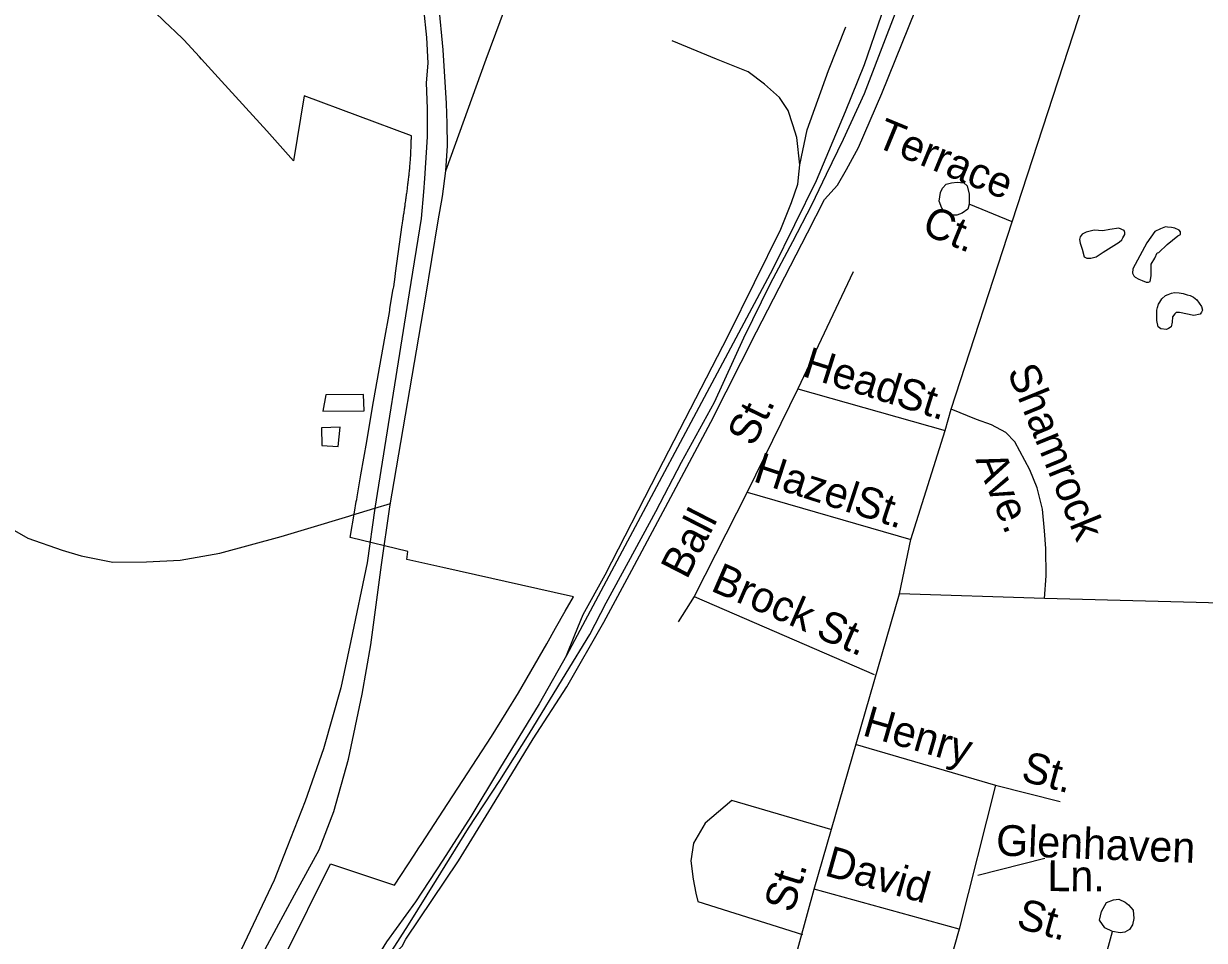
# Model space of a CAD drawing. Extents: x 2260773 to 2342389, y 552869 to 618546.
# Drawn here: x 2293706 to 2297350, y 585563 to 588391 of the extents above; entities that cross this region are included whole.
import ezdxf

# ---------------------------------------------------------------- set-up
doc = ezdxf.new("R2010")
doc.units = 0
for name, color, linetype in [('Exist Boundary Political City Limit New', 7, 'Continuous'), ('Exist Hydrographic Misc Water Feature', 7, 'Continuous'), ('Exist Railroad Mainline', 7, 'Continuous'), ('Exist Railroad Siding', 7, 'Continuous'), ('Exist Road Non-System Type 51', 7, 'Continuous'), ('Exist Road Non-System Type 51 Label', 7, 'Continuous'), ('Exist Road Primary Interstate Ramp 1 Lane Attributed', 7, 'Continuous'), ('Exist Road Primary US Divided Attributed', 7, 'Continuous'), ('Exist Road Secondary Type 51 Attributed', 7, 'Continuous'), ('Exist Road Secondary Type 51 Label', 7, 'Continuous'), ('Map Preparation Boundary City Limit Buffer Line', 7, 'Continuous')]:
    doc.layers.add(name, color=color, linetype=linetype)

msp = doc.modelspace()

# ---------------------------------------------------------------- linework, layer by layer
at = {"layer": 'Exist Boundary Political City Limit New'}
for points in [[(2294900.8, 587987.3), (2294901, 587991.9), (2294901.2, 587996.4), (2294901.2, 588001), (2294901.5, 588005.6), (2294901.8, 588010.1), (2294902, 588014.7), (2294902, 588019.2), (2294902.2, 588023.8), (2294902.2, 588031.8), (2294902.5, 588035.2), (2294902.5, 588044.1), (2294571.2, 588168.4), (2294538.2, 587967.1), (2294456.5, 588059.8), (2294316.8, 588213.4), (2294255.2, 588280.7), (2294248.8, 588287.8), (2294200.5, 588340.7), (2294171.2, 588368.8), (2294160.5, 588378.9), (2294066.2, 588469.2)], [(2294910.8, 585825.4), (2294925.8, 585848.2), (2294934.8, 585861.8), (2295000, 585961.2), (2295061.2, 586056.6), (2295150.2, 586192.3), (2295195.2, 586264.8), (2295233.2, 586326.2), (2295320.2, 586478), (2295347.5, 586525.8), (2295377.5, 586578.2), (2295402.8, 586622.4), (2295343, 586635.8), (2295000, 586713.1), (2294888, 586737.6), (2294891.2, 586762.5), (2294713.2, 586806.1), (2294726.8, 586883.3), (2294732.5, 586916.2), (2294733.8, 586923.3), (2294735, 586931.5), (2294746.8, 586998.9), (2294764.8, 587101.9), (2294783, 587207.3), (2294801.2, 587311.8), (2294819.5, 587415.3), (2294834.5, 587500), (2294835.8, 587506.8), (2294836, 587509.7), (2294836, 587511.6), (2294846, 587572.2), (2294847, 587574.9), (2294848.5, 587578.8), (2294852.2, 587610.1), (2294853.8, 587621.4), (2294874, 587769.7), (2294874.8, 587774.1), (2294875.5, 587777.6), (2294875.8, 587781), (2294876.5, 587784.4), (2294876.8, 587787.8), (2294877.5, 587792.3), (2294878.2, 587795.7), (2294878.5, 587799.1), (2294879.2, 587803.6), (2294879.8, 587807), (2294880.2, 587810.4), (2294880.5, 587811.5), (2294881, 587814.9), (2294881.5, 587819.4), (2294882, 587822.8), (2294882.5, 587826.2), (2294882.8, 587827.3), (2294883.2, 587830.8), (2294883.8, 587835.2), (2294884.5, 587839.8), (2294885, 587844.3), (2294885.8, 587848.8), (2294886.2, 587852.2), (2294886.5, 587855.6), (2294887.2, 587860.1), (2294887.8, 587864.7), (2294888.5, 587868.1), (2294889, 587871.4), (2294889.2, 587876), (2294890, 587880.5), (2294890.5, 587883.9), (2294890.8, 587887.3), (2294891.5, 587891.8), (2294891.8, 587893), (2294892, 587896.4), (2294892.5, 587899.8), (2294893, 587903.1), (2294893.5, 587907.7), (2294894, 587912.2), (2294894.5, 587915.6), (2294894.5, 587916.8), (2294894.8, 587917.9), (2294895, 587920.2), (2294895, 587921.3), (2294895.2, 587922.4), (2294895.5, 587924.7), (2294895.5, 587925.8), (2294895.8, 587927), (2294896, 587930.4), (2294896.5, 587934.9), (2294897, 587939.5), (2294897.5, 587942.9), (2294897.8, 587946.3), (2294898, 587949.7), (2294898.2, 587952), (2294898.2, 587953.1), (2294898.8, 587957.7), (2294899, 587961.1), (2294899.2, 587964.5), (2294899.5, 587968.9), (2294899.8, 587973.6), (2294900.2, 587978.2), (2294900.5, 587982.8), (2294900.8, 587987.3)], [(2294511.8, 585515.6), (2294653, 585798.9), (2294850.5, 585732.9), (2294910.8, 585825.4)]]:
    msp.add_lwpolyline(points, dxfattribs=at)
at = {"layer": 'Exist Hydrographic Misc Water Feature'}
for points in [[(2296964.5, 587724.7), (2296966.8, 587713.1), (2296972.7, 587695.1), (2296978.9, 587671.1), (2296986.7, 587667.1), (2296999.2, 587667.2), (2297015.2, 587671.3), (2297036.9, 587685.4), (2297086.7, 587716.1), (2297094.5, 587724.2), (2297098.4, 587730.1), (2297104.4, 587740.2), (2297104.2, 587746.3), (2297102.1, 587752.3), (2297085.9, 587760), (2297058, 587755.7), (2297036.1, 587751.7), (2297010, 587753.6), (2296984.4, 587747.3), (2296972.7, 587740.9), (2296966.4, 587733), (2296964.5, 587724.7)], [(2297196.4, 587749), (2297172.4, 587714.9), (2297129.2, 587634.6), (2297127.3, 587620.7), (2297131.4, 587612.4), (2297135.5, 587608.6), (2297147.4, 587602.7), (2297157.7, 587598.7), (2297170, 587592.8), (2297177.6, 587592.9), (2297181.9, 587595.1), (2297185.2, 587613.2), (2297185.4, 587639.2), (2297185.2, 587648.9), (2297197.1, 587667), (2297204.4, 587683.3), (2297208.7, 587685.2), (2297234.4, 587709.7), (2297268, 587735.8), (2297276, 587739.9), (2297276, 587748), (2297271.9, 587753.9), (2297258, 587759.6), (2297247.7, 587761.6), (2297236.2, 587763.3), (2297229.9, 587763.5), (2297213.9, 587757.3), (2297196.4, 587749)], [(2297326.2, 587538.5), (2297340.4, 587518.5), (2297344.3, 587506.6), (2297340.4, 587500.7), (2297336.3, 587494.8), (2297316.6, 587490.5), (2297272.7, 587499.9), (2297262.5, 587499.9), (2297258.4, 587496), (2297250.8, 587485.8), (2297250.6, 587470), (2297247.1, 587455.9), (2297238.9, 587449.9), (2297232.9, 587447.5), (2297214.9, 587449.4), (2297206.9, 587455.5), (2297202.6, 587475.2), (2297202.4, 587507.2), (2297204.6, 587515.4), (2297207.9, 587525.5), (2297212.4, 587531.3), (2297218.4, 587541.4), (2297229.9, 587551.8), (2297237.7, 587555.5), (2297247.7, 587559.6), (2297257.7, 587561.8), (2297271.9, 587560), (2297284, 587558.2), (2297296.1, 587554), (2297305.9, 587552.1), (2297316, 587546.5), (2297326.2, 587538.5)], [(2294628.8, 587195.3), (2294756.5, 587196.7), (2294754.3, 587246.6), (2294638.4, 587245.3), (2294628.8, 587195.3)], [(2294626.1, 587089.4), (2294676.1, 587086), (2294683.1, 587145.8), (2294625.3, 587143.5), (2294626.1, 587089.4)]]:
    msp.add_lwpolyline(points, dxfattribs=at)
at = {"layer": 'Exist Railroad Mainline'}
for points in [[(2296169.2, 591130), (2296437.4, 589781.5), (2296454.2, 589709.6), (2296468.7, 589647.9), (2296473.4, 589565.9), (2296486.4, 589464), (2296493.5, 589340.1), (2296498.4, 589238.3), (2296491.7, 589102.3), (2296481, 588970.3), (2296466, 588852.3), (2296437.4, 588714.1), (2296406.6, 588591.8), (2296352.2, 588415.3), (2296299.8, 588263.1), (2296241.1, 588118.5), (2296151.2, 587905.8), (2296017.8, 587634.6), (2295381.3, 586441.3)], [(2294816.7, 585490.5), (2294893.5, 585611.1), (2294980.1, 585749.9), (2295078.7, 585908.9), (2295175.2, 586055.7), (2295265.7, 586200.4), (2295379.8, 586387.4), (2295452.8, 586506.1), (2295503.8, 586604.4), (2295572.5, 586731), (2295657, 586885.8), (2295735.6, 587038.3), (2295837.7, 587223.2), (2295927.9, 587421.9), (2296010.2, 587588.6), (2296079.1, 587719.1), (2296137.9, 587831.7), (2296183, 587926.2), (2296236, 588034.4), (2296300.6, 588175.1), (2296370.9, 588357.6), (2296454.6, 588576.2)], [(2295381.3, 586441.3), (2295296.9, 586292.7), (2295174.7, 586091.7), (2295086.2, 585944.9), (2294999.5, 585810.1), (2294914.7, 585681.5), (2294826.1, 585558.5), (2294735.3, 585411.8)]]:
    msp.add_lwpolyline(points, dxfattribs=at)
at = {"layer": 'Exist Railroad Siding'}
for points in [[(2294816.7, 585490.5), (2294874.2, 585545.1), (2294885.8, 585567.1), (2295047.4, 585808.5), (2295149.9, 585973.4), (2295278, 586184.5), (2295382.4, 586345.4), (2295496.3, 586544.4), (2295582.8, 586705.2), (2295702.7, 586930.1), (2295826.3, 587161.1), (2295967.7, 587440.3), (2296124.8, 587745.6), (2296177.6, 587848.1), (2296217.3, 587892.5), (2296244.9, 587940.7), (2296282.2, 588008.9), (2296354.6, 588175.6), (2296563.6, 588695.2)], [(2296100.8, 587955.2), (2296123.8, 588063.5), (2296190.1, 588245.9), (2296242.8, 588380.4)], [(2296100.8, 587955.2), (2296091.9, 588039.2), (2296079.5, 588079), (2296065.2, 588122.9), (2296038.8, 588162.6), (2295992.5, 588204.1), (2295942.1, 588241.7), (2295843.9, 588280.7), (2295707.3, 588337.4)], [(2295381.3, 586441.3), (2295406.8, 586505.6), (2295432.2, 586567.7), (2295500.9, 586690.4), (2295663.9, 587009.6), (2295879.8, 587427.5), (2296042.6, 587756.9), (2296075.9, 587839.2), (2296095.4, 587895.3), (2296099, 587935.3), (2296100.8, 587955.2)]]:
    msp.add_lwpolyline(points, dxfattribs=at)
at = {"layer": 'Exist Road Non-System Type 51'}
for p, q in [((2296756, 587779.6), (2296623.6, 587834.3)), ((2296266.2, 587625.5), (2296095.3, 587263.7)), ((2296095.3, 587263.7), (2295938.7, 586945.1)), ((2296095.3, 587263.7), (2296549.4, 587135.8)), ((2295938.7, 586945.1), (2295775.5, 586623.6)), ((2295938.7, 586945.1), (2296443.7, 586799.5)), ((2294790, 586896.3), (2294837.8, 586910.7)), ((2294583.1, 586833.8), (2294709, 586871.8)), ((2294709, 586871.8), (2294718.5, 586874.7)), ((2294718.5, 586874.7), (2294790, 586896.3)), ((2295775.5, 586623.6), (2295725.9, 586545.2)), ((2295775.5, 586623.6), (2296330.2, 586383.3)), ((2296271.5, 586168.5), (2296704.8, 586041.8)), ((2296704.8, 586041.8), (2296592.5, 585597.9)), ((2296704.8, 586041.8), (2296904.4, 585990.9)), ((2296592.5, 585597.9), (2296145.8, 585721)), ((2296592.5, 585597.9), (2296468.5, 585159.7))]:
    msp.add_line(p, q, dxfattribs=at)
for points in [[(2296623.6, 587834.3), (2296619.8, 587818.2), (2296601.8, 587806.1), (2296585.9, 587799.9), (2296567.9, 587799.8), (2296549.9, 587807.6), (2296539.7, 587821.6), (2296531.6, 587843.3), (2296535.3, 587869.5), (2296541.2, 587883.5), (2296553, 587895.5), (2296568.9, 587899.8), (2296587, 587901.8), (2296606.9, 587900), (2296617.1, 587890.2), (2296623.4, 587864.3), (2296623.6, 587834.3)], [(2296856.1, 586617), (2296861.4, 586687.6), (2296860.1, 586771.5), (2296856.1, 586826.3), (2296850.2, 586892.9), (2296833.8, 586958.8), (2296811.1, 587014.4), (2296764.8, 587100.5), (2296737.4, 587129.2), (2296693, 587152.8), (2296646, 587169.7), (2296567.7, 587201.1)], [(2300809, 587184.6), (2300455.1, 587076.9), (2300325.3, 587042), (2300126.7, 586986.5), (2299640.5, 586848.9), (2299264.2, 586746.4), (2298958.6, 586655), (2298809.6, 586614), (2298742.5, 586595.4), (2298691.2, 586583.3), (2298580.2, 586579.4), (2298180.8, 586582.8), (2296856.1, 586617), (2296408.5, 586631.4)], [(2293518, 586913.7), (2293636.5, 586850.7), (2293718.9, 586803.6), (2293825.3, 586766.5), (2293883.3, 586749.1), (2293981.5, 586729.9), (2294085.5, 586731), (2294189.3, 586735.9), (2294311.1, 586757.1), (2294500.5, 586808.8), (2294583.1, 586833.8)], [(2296197.1, 585905.4), (2295891.7, 585994.8), (2295809.5, 585924.3), (2295772.9, 585862.9), (2295765.1, 585808.1), (2295771.6, 585751.9), (2295780.7, 585708.8), (2295786, 585682.7), (2296109.6, 585581.5)], [(2297066.3, 585590), (2297042.1, 585601.7), (2297025.8, 585625.6), (2297031.8, 585651.7), (2297047.3, 585679.7), (2297069.3, 585687.9), (2297085.3, 585690.2), (2297105.3, 585680.4), (2297115.3, 585672.4), (2297129.6, 585656.5), (2297131.9, 585630.4), (2297128.1, 585610.5), (2297118.2, 585596.3), (2297104.2, 585588.2), (2297090.2, 585586.1), (2297066.3, 585590)], [(2296916.2, 585034.4), (2297032.3, 585466), (2297066.3, 585590)]]:
    msp.add_lwpolyline(points, dxfattribs=at)
at = {"layer": 'Exist Road Non-System Type 51 Label'}
msp.add_lwpolyline([(2296856.9, 585815.9), (2296650.9, 585763.4)], dxfattribs=at)
at = {"layer": 'Exist Road Primary Interstate Ramp 1 Lane Attributed'}
msp.add_lwpolyline([(2295008.7, 587936.6), (2295133.7, 588281), (2295236.5, 588558.6), (2295262.7, 588657.6)], dxfattribs=at)
at = {"layer": 'Exist Road Primary US Divided Attributed'}
for points in [[(2294939.6, 588436.6), (2294949, 588347.5), (2294953.2, 588268.8), (2294948, 588208.1), (2294951.4, 588128.8), (2294951.4, 588041), (2294942.9, 587912.8), (2294939.6, 587872.3), (2294932.8, 587789.6), (2294895.7, 587560), (2294790, 586896.3), (2294766.2, 586728), (2294715.2, 586486.6), (2294684.9, 586341.5), (2294630.9, 586154.1), (2294575.2, 585992.1), (2294517.9, 585848.7), (2294479.1, 585749.1), (2294367.8, 585514.5)], [(2295008.7, 587936.6), (2295013.8, 588013.7), (2295012.5, 588082.5), (2295010.4, 588143.9), (2295000.1, 588310.1), (2294987, 588450.1)], [(2293381.4, 584211.6), (2293482.8, 584294.2), (2293779.3, 584588.3), (2294014.7, 584847), (2294200.8, 585101), (2294323.9, 585298.5), (2294430.2, 585497.6), (2294541.5, 585703.5), (2294617.4, 585841.9), (2294662.9, 585960), (2294708.5, 586122.1), (2294750.7, 586322.9), (2294777.6, 586474.8), (2294810.6, 586721.2), (2294836, 586900.3), (2294945.7, 587543.4), (2294985.3, 587782.5), (2294998.4, 587857.7), (2295008.7, 587936.6)]]:
    msp.add_lwpolyline(points, dxfattribs=at)
at = {"layer": 'Exist Road Secondary Type 51 Attributed'}
msp.add_lwpolyline([(2295809.5, 584493.6), (2296145.8, 585721), (2296408.5, 586631.4), (2296443.7, 586799.5), (2296549.4, 587135.8), (2296567.7, 587201.1), (2296756, 587779.6), (2297102.8, 588842.5), (2297171.1, 589045.3), (2297271.2, 589353.1), (2297362.5, 589635.1), (2297469.5, 589959.6), (2297516.5, 590114.3), (2297577.9, 590282.8), (2297741, 590769.2), (2297878, 591142)], dxfattribs=at)
at = {"layer": 'Map Preparation Boundary City Limit Buffer Line'}
for points in [[(2294900.8, 587987.3), (2294901, 587991.9), (2294901.2, 587996.4), (2294901.2, 588001), (2294901.5, 588005.6), (2294901.8, 588010.1), (2294902, 588014.7), (2294902, 588019.2), (2294902.2, 588023.8), (2294902.2, 588031.8), (2294902.5, 588035.2), (2294902.5, 588044.1), (2294571.2, 588168.4), (2294538.2, 587967.1), (2294456.5, 588059.8), (2294316.8, 588213.4), (2294255.2, 588280.7), (2294248.8, 588287.8), (2294200.5, 588340.7), (2294171.2, 588368.8), (2294160.5, 588378.9), (2294066.2, 588469.2)], [(2294910.8, 585825.4), (2294925.8, 585848.2), (2294934.8, 585861.8), (2295000, 585961.2), (2295061.2, 586056.6), (2295150.2, 586192.3), (2295195.2, 586264.8), (2295233.2, 586326.2), (2295320.2, 586478), (2295347.5, 586525.8), (2295377.5, 586578.2), (2295402.8, 586622.4), (2295343, 586635.8), (2295000, 586713.1), (2294888, 586737.6), (2294891.2, 586762.5), (2294713.2, 586806.1), (2294726.8, 586883.3), (2294732.5, 586916.2), (2294733.8, 586923.3), (2294735, 586931.5), (2294746.8, 586998.9), (2294764.8, 587101.9), (2294783, 587207.3), (2294801.2, 587311.8), (2294819.5, 587415.3), (2294834.5, 587500), (2294835.8, 587506.8), (2294836, 587509.7), (2294836, 587511.6), (2294846, 587572.2), (2294847, 587574.9), (2294848.5, 587578.8), (2294852.2, 587610.1), (2294853.8, 587621.4), (2294874, 587769.7), (2294874.8, 587774.1), (2294875.5, 587777.6), (2294875.8, 587781), (2294876.5, 587784.4), (2294876.8, 587787.8), (2294877.5, 587792.3), (2294878.2, 587795.7), (2294878.5, 587799.1), (2294879.2, 587803.6), (2294879.8, 587807), (2294880.2, 587810.4), (2294880.5, 587811.5), (2294881, 587814.9), (2294881.5, 587819.4), (2294882, 587822.8), (2294882.5, 587826.2), (2294882.8, 587827.3), (2294883.2, 587830.8), (2294883.8, 587835.2), (2294884.5, 587839.8), (2294885, 587844.3), (2294885.8, 587848.8), (2294886.2, 587852.2), (2294886.5, 587855.6), (2294887.2, 587860.1), (2294887.8, 587864.7), (2294888.5, 587868.1), (2294889, 587871.4), (2294889.2, 587876), (2294890, 587880.5), (2294890.5, 587883.9), (2294890.8, 587887.3), (2294891.5, 587891.8), (2294891.8, 587893), (2294892, 587896.4), (2294892.5, 587899.8), (2294893, 587903.1), (2294893.5, 587907.7), (2294894, 587912.2), (2294894.5, 587915.6), (2294894.5, 587916.8), (2294894.8, 587917.9), (2294895, 587920.2), (2294895, 587921.3), (2294895.2, 587922.4), (2294895.5, 587924.7), (2294895.5, 587925.8), (2294895.8, 587927), (2294896, 587930.4), (2294896.5, 587934.9), (2294897, 587939.5), (2294897.5, 587942.9), (2294897.8, 587946.3), (2294898, 587949.7), (2294898.2, 587952), (2294898.2, 587953.1), (2294898.8, 587957.7), (2294899, 587961.1), (2294899.2, 587964.5), (2294899.5, 587968.9), (2294899.8, 587973.6), (2294900.2, 587978.2), (2294900.5, 587982.8), (2294900.8, 587987.3)], [(2294511.8, 585515.6), (2294653, 585798.9), (2294850.5, 585732.9), (2294910.8, 585825.4)]]:
    msp.add_lwpolyline(points, dxfattribs=at)

# ---------------------------------------------------------------- texts
at = {"layer": 'Exist Road Non-System Type 51 Label'}
for s, rotation, p in [('Terrace', 337.5533, (2296329.9, 588013.6)), ('Ct.', 337.5533, (2296473.3, 587744.7)), ('Head', 342.4383, (2296105.6, 587304.5)), ('Shamrock', 292.2089, (2296740.2, 587318.3)), ('St.', 342.4383, (2296393, 587213.6)), ('St.', 64.1124, (2295958.8, 587082.9)), ('Hazel', 341.9177, (2295953.9, 586979.9)), ('Ave.', 292.2089, (2296642.3, 587046.3)), ('St.', 341.9177, (2296262.3, 586880.6)), ('Ball', 62.8459, (2295752.4, 586673.5)), ('Brock', 336.4679, (2295822.7, 586642.9)), ('St.', 336.4679, (2296146.5, 586500.1)), ('Henry', 343.8918, (2296291, 586196.4)), ('St.', 344.9521, (2296780.1, 586056.7)), ('Glenhaven', 357.8199, (2296705.6, 585825.1)), ('David', 344.3263, (2296173.8, 585764.3)), ('Ln.', 359.9048, (2296865.2, 585714.8)), ('St.', 344.4258, (2296765.7, 585602.9))]:
    msp.add_text(s, height=95, rotation=rotation, dxfattribs=at).set_placement(p)
at = {"layer": 'Exist Road Secondary Type 51 Label'}
msp.add_text('St.', height=95, rotation=72.9069, dxfattribs=at).set_placement((2296079.4, 585644.9))

doc.saveas('drawing.dxf')
